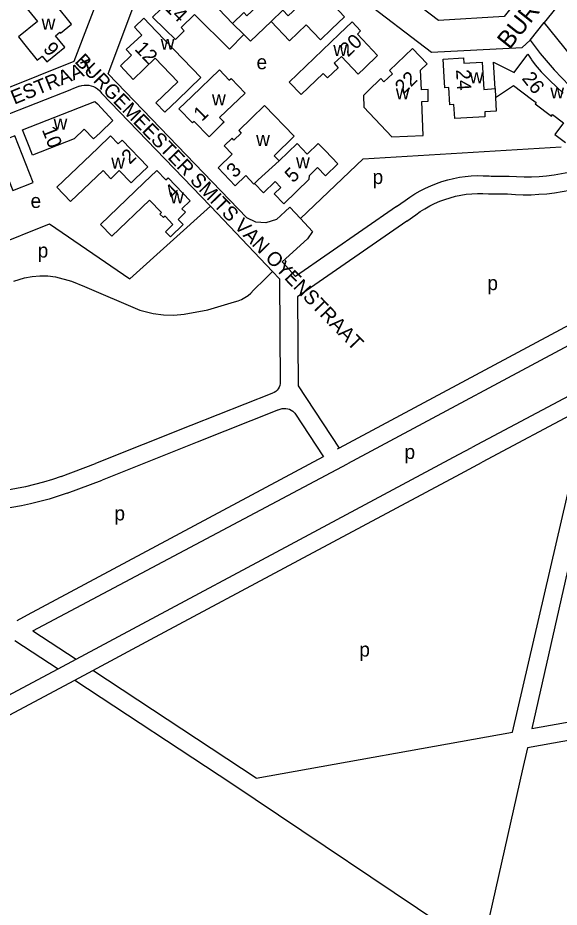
# Model space of a CAD drawing. Extents: x 159261 to 160849, y 382514 to 384534.
# Drawn here: x 159856 to 160007.7, y 382712.8 to 382961.9 of the extents above; entities that cross this region are included whole.
import ezdxf

# ---------------------------------------------------------------- set-up
doc = ezdxf.new("R2010")
doc.units = 0
for name, color, linetype in [('BLT_Basislijn', 7, 'Continuous'), ('BLT_Bebouwing', 7, 'Continuous'), ('BLT_Centroide', 7, 'Continuous'), ('BLT_Huisnummer', 7, 'Continuous'), ('BLT_Onderverdeling_panden', 7, 'Continuous'), ('BLT_Straatnaam', 7, 'Continuous'), ('BLT_Straatnaam_verkleind', 7, 'Continuous')]:
    doc.layers.add(name, color=color, linetype=linetype)

msp = doc.modelspace()

# ---------------------------------------------------------------- linework, layer by layer
at = {"layer": 'BLT_Basislijn'}
for p, q in [((160058.23, 383028.61), (160003.53, 382960.61)), ((159933.17, 382982), (159971.93, 382952.26)), ((159881.27, 382946.18), (159890.56, 382970.79)), ((159999.6, 382955.67), (160003.53, 382960.61)), ((159997.39, 382953.55), (159999.6, 382955.67)), ((159999.6, 382955.67), (160002.39, 382951.92)), ((159971.93, 382952.26), (159997.39, 382953.55)), ((160002.39, 382951.92), (160006.35, 382947.38)), ((160006.35, 382947.38), (160012.81, 382940.59)), ((159920.18, 382905.9), (159881.27, 382946.18)), ((159851.1, 382934.1), (159871.08, 382941.92)), ((159873.23, 382942.8), (159871.08, 382941.92)), ((159879.48, 382940.84), (159909.96, 382909.12)), ((159952.75, 382922.39), (160008.31, 382925.74)), ((159935.18, 382905.66), (159952.75, 382922.39)), ((159988.65, 382917.56), (159993.68, 382917.56)), ((159988.2, 382912.58), (159993.25, 382912.58)), ((159962.17, 382909.1), (159964.52, 382910.72)), ((159909.96, 382909.12), (159913.63, 382905.31)), ((159930.88, 382907.65), (159928.49, 382905.42)), ((159932.19, 382908.9), (159930.88, 382907.65)), ((159935.18, 382905.66), (159932.19, 382908.9)), ((159962.17, 382909.1), (159933.81, 382889.44)), ((159913.63, 382905.31), (159927.36, 382890.87)), ((159922.66, 382904.66), (159920.18, 382905.9)), ((159925.52, 382904.47), (159922.66, 382904.66)), ((159928.49, 382905.42), (159925.52, 382904.47)), ((159965.02, 382904.99), (159934.37, 382883.74)), ((159965.02, 382904.99), (159967.52, 382906.72)), ((159930.1, 382893.52), (159933.81, 382889.44)), ((159927.36, 382890.87), (159929.33, 382888.8)), ((159929.33, 382888.8), (159929.53, 382859.47)), ((159934.37, 382883.74), (159934.54, 382858.83)), ((160017.32, 382859.71), (159983.24, 382841.55)), ((159934.54, 382858.83), (159946.06, 382841.36)), ((159927.22, 382856.72), (159904.44, 382847.69)), ((160015.85, 382853.26), (159986.11, 382837.42)), ((159929.07, 382852.07), (159906.28, 382843.04)), ((159933.6, 382851.17), (159941.63, 382838.99)), ((159904.44, 382847.69), (159877.74, 382837.04)), ((159906.28, 382843.04), (159879.6, 382832.4)), ((159946.06, 382841.36), (159945.52, 382841.08)), ((159979.5, 382839.57), (159983.24, 382841.55)), ((159932.41, 382814.4), (159979.5, 382839.57)), ((159941.63, 382838.99), (159941.53, 382838.94)), ((159980.1, 382834.22), (159986.11, 382837.42)), ((159860.15, 382790.19), (159948.41, 382836.95)), ((159868.11, 382833.46), (159877.74, 382837.04)), ((159869.8, 382828.75), (159879.6, 382832.4)), ((159934.76, 382809.99), (159980.1, 382834.22)), ((159890.82, 382792.19), (159932.41, 382814.4)), ((159893.17, 382787.78), (159934.76, 382809.99)), ((159860.15, 382790.19), (159872.34, 382782.31)), ((159872.34, 382782.31), (159890.82, 382792.19)), ((159855.11, 382787.5), (159867.3, 382779.61)), ((159876.98, 382779.12), (159893.17, 382787.78)), ((159867.3, 382779.61), (159872.34, 382782.31)), ((159849.56, 382770.13), (159867.3, 382779.61)), ((159871.96, 382776.44), (159876.98, 382779.12)), ((159922.81, 382748.95), (159876.98, 382779.12)), ((159852.2, 382765.87), (159871.96, 382776.44)), ((159998.83, 382757.49), (159997.36, 382750.97)), ((159997.36, 382750.97), (159983.99, 382691.71))]:
    msp.add_line(p, q, dxfattribs=at)
for points in [[(160042.91, 383029.03), (160043.3, 383028.51), (160043.47, 383027.9), (160043.44, 383027.23), (160043.27, 383026.57), (160040.7, 383022.91), (159992.33, 382962.32), (159973.92, 382961.19), (159954.84, 382975.74), (159937.58, 382989.45), (159937.15, 382990.12), (160001.27, 383055.05), (160002.23, 383055.6), (160003.22, 383055.89), (160004.3, 383055.97), (160005.53, 383055.68), (160014.56, 383049.24)], [(159804.96, 382923.13), (159812.17, 382925.83), (159871.81, 382949.78), (159881.19, 382974.39)], [(160023.71, 382939.02), (160018.92, 382943.04), (160012.93, 382948.97), (160003.53, 382960.61)], [(159873.23, 382942.8), (159873.88, 382942.97), (159874.54, 382943.07), (159875.21, 382943.08), (159875.87, 382943.02), (159876.52, 382942.87), (159877.15, 382942.65), (159877.75, 382942.36), (159878.31, 382942), (159878.83, 382941.57), (159879.29, 382941.08), (159879.48, 382940.84)], [(159964.52, 382910.72), (159965.88, 382911.7), (159967.29, 382912.6), (159968.74, 382913.43), (159970.22, 382914.2), (159971.74, 382914.89), (159973.3, 382915.51), (159974.88, 382916.06), (159976.48, 382916.53), (159978.1, 382916.92), (159979.75, 382917.23), (159981.4, 382917.47), (159983.07, 382917.62), (159984.74, 382917.7), (159986.41, 382917.69), (159988.08, 382917.61), (159988.65, 382917.56)], [(159993.68, 382917.56), (159995.78, 382917.42), (159997.88, 382917.36), (159999.99, 382917.38), (160002.09, 382917.48), (160004.19, 382917.66), (160006.28, 382917.92), (160008.36, 382918.26), (160010.42, 382918.67), (160012.47, 382919.17), (160013.15, 382919.35)], [(159993.25, 382912.58), (159995.44, 382912.43), (159997.64, 382912.36), (159999.84, 382912.37), (160002.04, 382912.47), (160004.23, 382912.64), (160006.41, 382912.89), (160008.58, 382913.22), (160010.74, 382913.63), (160012.89, 382914.11), (160014.47, 382914.53)], [(159967.52, 382906.72), (159968.78, 382907.62), (159970.09, 382908.45), (159971.44, 382909.21), (159972.82, 382909.9), (159974.24, 382910.52), (159975.69, 382911.06), (159977.16, 382911.53), (159978.66, 382911.92), (159980.18, 382912.23), (159981.7, 382912.47), (159983.24, 382912.62), (159984.79, 382912.7), (159986.34, 382912.69), (159987.88, 382912.61), (159988.2, 382912.58)], [(159848.75, 382898.48), (159848.97, 382897.9), (159864.82, 382904.2), (159887.39, 382888.81), (159909.96, 382909.12)], [(159935.18, 382905.66), (159938.58, 382902.08), (159937.14, 382900), (159930.1, 382893.52)], [(159854.89, 382888.14), (159857.84, 382889.09), (159859.99, 382889.49), (159862.17, 382889.67), (159864.36, 382889.61), (159866.52, 382889.33), (159871, 382888.12), (159874.69, 382886.66), (159890.22, 382879.99), (159893.9, 382879.06), (159896.8, 382878.69), (159899.73, 382878.62), (159902.65, 382878.86), (159909.22, 382880.12), (159916.71, 382882.33), (159917.72, 382882.63), (159918.71, 382883.03), (159919.64, 382883.54), (159920.52, 382884.14), (159921.33, 382884.83), (159922.06, 382885.6), (159925.3, 382888.82), (159927.36, 382890.87)], [(160022.51, 382882.25), (159946.06, 382841.36)], [(160021.02, 382875.78), (159948.41, 382836.95)], [(159929.53, 382859.47), (159929.43, 382858.97), (159929.25, 382858.48), (159928.99, 382858.04), (159928.67, 382857.63), (159928.29, 382857.28), (159927.87, 382856.99), (159927.4, 382856.78), (159927.22, 382856.72)], [(160021.17, 382856.09), (160000.04, 382762.82), (160136.27, 382787.12), (160144.29, 382788.53)], [(159922.81, 382748.95), (159994.67, 382761.8), (160015.85, 382853.26)], [(159929.07, 382852.07), (159929.55, 382852.29), (159930.06, 382852.44), (159930.59, 382852.52), (159931.12, 382852.51), (159931.65, 382852.42), (159932.16, 382852.26), (159932.64, 382852.02), (159933.07, 382851.71), (159933.46, 382851.34), (159933.6, 382851.17)], [(159941.53, 382838.94), (159858.63, 382794.61), (159855.75, 382793.04)], [(159868.11, 382833.46), (159865.67, 382832.63), (159863.19, 382831.87), (159860.69, 382831.19), (159858.18, 382830.58), (159855.64, 382830.06), (159853.09, 382829.61), (159850.53, 382829.24), (159848.5, 382829.01)], [(159869.8, 382828.75), (159867.28, 382827.89), (159864.73, 382827.11), (159862.16, 382826.4), (159859.57, 382825.77), (159856.97, 382825.22), (159854.34, 382824.75), (159851.71, 382824.35), (159849.02, 382824.03)], [(160137.38, 382782.24), (160115.57, 382778.37), (159998.83, 382757.49)], [(159871.96, 382776.44), (159915.96, 382747.47), (159981.1, 382703.75), (159977.76, 382688.38)]]:
    msp.add_lwpolyline(points, dxfattribs=at)
at = {"layer": 'BLT_Bebouwing'}
for p, q in [((159921.16, 382955.33), (159926.98, 382960.92)), ((159921.16, 382955.33), (159919.29, 382957.19)), ((160002.7, 382946.81), (160005.09, 382944.37)), ((160005.09, 382944.37), (160008.85, 382940.79))]:
    msp.add_line(p, q, dxfattribs=at)
for points in [[(159916.13, 382960.32), (159919.33, 382963.35), (159920.21, 382962.42), (159923.87, 382965.89), (159920.76, 382969.09), (159920.25, 382968.59), (159917.25, 382971.68), (159918.39, 382972.78), (159914.88, 382976.4), (159916.39, 382977.86), (159919.89, 382974.24), (159923.13, 382977.38), (159924.66, 382975.81), (159925.6, 382976.73), (159926.86, 382975.43), (159930.52, 382978.98), (159936.42, 382972.89), (159932.24, 382968.86), (159933.66, 382967.34), (159930.23, 382964.04)], [(159919.29, 382957.19), (159915.3, 382953.17), (159905.51, 382962.88), (159901.8, 382959.15), (159902.65, 382958.3), (159900.16, 382955.79), (159897.31, 382958.61), (159893.76, 382962.13), (159896.1, 382964.36), (159895.28, 382965.22), (159898.93, 382968.72), (159899.76, 382967.85), (159904.62, 382972.46), (159916.13, 382960.32)], [(159926.98, 382960.92), (159932.16, 382955.49), (159936.83, 382959.95), (159940.81, 382955.77), (159943.94, 382958.76), (159947.55, 382962.21), (159944.65, 382965.23), (159946.26, 382966.79), (159941.35, 382971.93), (159934.11, 382965), (159934.29, 382964.79), (159931.77, 382962.42), (159930.23, 382964.04)], [(159860.73, 382971.35), (159856.08, 382967.55), (159861.49, 382960.92), (159856.13, 382956.55), (159858.28, 382953.91), (159861.44, 382950.04), (159862.8, 382951.17), (159864.16, 382949.56), (159869.15, 382953.66), (159866.51, 382956.9), (159867.72, 382957.88), (159867.95, 382957.6), (159871.06, 382960.14), (159866.84, 382965.31), (159866.13, 382964.72), (159860.73, 382971.35)], [(159900.83, 382938.91), (159907.31, 382945.18), (159894.76, 382958.21), (159891.29, 382961.81), (159888.65, 382959.26), (159890.71, 382957.09), (159886.37, 382953.02), (159887.88, 382951.45), (159884.74, 382948.42), (159888.35, 382944.66), (159894.5, 382950.57), (159900.81, 382943.99), (159894.67, 382938.1), (159897.23, 382935.44), (159900.83, 382938.91)], [(159953.26, 382947.88), (159951.4, 382946.08), (159946.68, 382951.1), (159944.62, 382949.17), (159945.78, 382947.93), (159942.81, 382945.14), (159941.6, 382946.35), (159935.38, 382940.4), (159932.01, 382943.9), (159946.06, 382957.31), (159949.68, 382960.76), (159952.06, 382958.27), (159951.15, 382957.33), (159956.84, 382951.36), (159953.26, 382947.88)], [(159970.97, 382938.57), (159970.97, 382941.8), (159969.12, 382941.76), (159968.86, 382947.24), (159970.76, 382949.01), (159966.6, 382953.34), (159960.13, 382947.17), (159960.98, 382946.26), (159958.6, 382943.95), (159957.75, 382944.89), (159954.14, 382941.43), (159952.84, 382940.19), (159952.98, 382936.87), (159960.85, 382928.58), (159969.64, 382928.96), (159969.25, 382938.5), (159970.97, 382938.57)], [(159989.9, 382939.63), (159990.07, 382935.74), (159986.85, 382935.55), (159986.93, 382934.2), (159978.46, 382933.66), (159978.21, 382937.63), (159977.09, 382937.56), (159976.79, 382942.39), (159975.68, 382942.31), (159975.5, 382945.34), (159975.21, 382950.33), (159980.91, 382950.67), (159981.03, 382949.2), (159986.12, 382949.51), (159986.57, 382941.87), (159989.78, 382942.08)], [(159989.78, 382942.08), (159989.32, 382949.49), (159995.13, 382946.61), (159998.93, 382951.68)], [(159998.93, 382951.68), (159999.89, 382950.28), (160000, 382950.12)], [(160000, 382950.12), (160001.03, 382948.77), (160002.12, 382947.46), (160002.7, 382946.81)], [(159913.81, 382932.69), (159913.3, 382932.19), (159913.18, 382932.08), (159909.59, 382928.61), (159905.37, 382932.91), (159904.95, 382932.51), (159901.14, 382936.45), (159904.76, 382939.91), (159912.54, 382947.34), (159915.25, 382944.48), (159915.74, 382944.94), (159919.67, 382940.8), (159912.53, 382934.03), (159913.81, 382932.69)], [(159989.9, 382939.63), (159994.95, 382942.92), (160000, 382939.16), (160001.28, 382938.21), (160000.99, 382937.83), (160005.57, 382934.39), (160005.85, 382934.79), (160008.97, 382932.45), (160006.52, 382929.19), (160009.5, 382926.95)], [(159879.02, 382929.73), (159877.19, 382927.98), (159874.56, 382930.72), (159871.76, 382928.03), (159860.1, 382923.47), (159859.15, 382925.89), (159857.33, 382930.55), (159877.54, 382938.46), (159878.3, 382937.78), (159882.63, 382933.19), (159879.02, 382929.73)], [(159929.22, 382921.83), (159927.82, 382923.28), (159933.46, 382928.72), (159925.15, 382937.34), (159925.15, 382937.33), (159925.16, 382937.32), (159921.52, 382933.81), (159917.93, 382930.32), (159918.6, 382929.64), (159916.54, 382927.68), (159916.06, 382928.22), (159913.83, 382926.03), (159916.05, 382923.73), (159912.1, 382919.93), (159916.93, 382914.89), (159919.86, 382917.72), (159922.16, 382915.34), (159922.3, 382915.48)], [(159847.59, 382925.89), (159847.89, 382925.13), (159842.43, 382923), (159846.05, 382913.77), (159853.39, 382916.64), (159854.6, 382913.55), (159860.26, 382915.77), (159855.15, 382928.82), (159847.59, 382925.89)], [(159888.82, 382916.7), (159887.74, 382915.66), (159884.42, 382919.13), (159882.08, 382916.83), (159879.86, 382919.15), (159870.78, 382910.47), (159866.95, 382914.47), (159878.37, 382925.4), (159881.98, 382928.86), (159884.13, 382926.62), (159885.22, 382927.66), (159892.43, 382920.16), (159888.82, 382916.7)], [(159922.3, 382915.48), (159924.83, 382912.87), (159928.1, 382916.05), (159929.69, 382914.41), (159927.83, 382912.6), (159930.55, 382909.8), (159937.69, 382916.69), (159937.72, 382917.78), (159939.98, 382919.99), (159942.22, 382917.66), (159945.65, 382921.05), (159942.18, 382924.64), (159940.17, 382926.73), (159937.08, 382923.75), (159934.24, 382926.69), (159929.22, 382921.83)], [(159900.93, 382905.46), (159902.3, 382904.01), (159898.75, 382900.54), (159897.34, 382901.98), (159899.45, 382904.05), (159897.24, 382906.37), (159896.8, 382905.95), (159895.79, 382906.95), (159896.24, 382907.39), (159892.87, 382910.83), (159882.3, 382900.73), (159879.16, 382904.01), (159891.33, 382915.66), (159894.94, 382919.12), (159897.45, 382916.51), (159898.09, 382917.11), (159904.32, 382910.65), (159901.99, 382908.4), (159902.99, 382907.43), (159900.93, 382905.46)]]:
    msp.add_lwpolyline(points, dxfattribs=at)
at = {"layer": 'BLT_Onderverdeling_panden'}
for p, q in [((159926.98, 382960.92), (159930.23, 382964.04)), ((159919.29, 382957.19), (159916.13, 382960.32)), ((159989.78, 382942.08), (159989.9, 382939.63))]:
    msp.add_line(p, q, dxfattribs=at)
msp.add_lwpolyline([(159929.22, 382921.83), (159923.31, 382916.49), (159922.3, 382915.48)], dxfattribs=at)

# ---------------------------------------------------------------- texts
at = {"layer": 'BLT_Centroide'}
for s, p in [('w', (159862.64, 382958.58)), ('w', (159896.03, 382952.94)), ('w', (159944.42, 382951.2)), ('e', (159922.9, 382947.5)), ('w', (159982.64, 382943.59)), ('w', (159961.93, 382939.12)), ('w', (160005.25, 382939.31)), ('w', (159910.41, 382937.36)), ('w', (159866, 382930.62)), ('w', (159922.78, 382926.03)), ('w', (159882.16, 382919.69)), ('w', (159933.97, 382919.77)), ('p', (159955.42, 382915.36)), ('w', (159898.66, 382909.94)), ('e', (159859.55, 382908.65)), ('p', (159861.55, 382894.76)), ('p', (159987.6, 382885.64)), ('p', (159964.38, 382838.35)), ('p', (159883.06, 382821.14)), ('p', (159951.69, 382783.01))]:
    msp.add_text(s, height=4, dxfattribs=at).set_placement(p)
at = {"layer": 'BLT_Huisnummer'}
for s, rotation, p in [('14', 315.235, (159896.89, 382964.52)), ('20', 44.1075, (159948.55, 382950.74)), ('9', 309.178, (159862.89, 382953.11)), ('12', 313.8175, (159888.51, 382953.02)), ('24', 273.3287, (159978.81, 382947.37)), ('22', 44.0112, (159964.02, 382940.3)), ('26', 308.1756, (159997.1, 382944.88)), ('1', 44.054, (159907.57, 382932.71)), ('10', 291.3609, (159862.67, 382930.6)), ('2', 43.8087, (159887.35, 382920.71)), ('3', 43.8177, (159916.77, 382916.86)), ('5', 43.9836, (159933.13, 382915.49)), ('4', 43.6558, (159899.47, 382910.88))]:
    msp.add_text(s, height=4, rotation=rotation, dxfattribs=at).set_placement(p)
at = {"layer": 'BLT_Straatnaam'}
msp.add_text('BURGEMEESTER WITTESTRAAT', height=5, rotation=51.4824, dxfattribs=at).set_placement((159993.82, 382952.82))
at = {"layer": 'BLT_Straatnaam_verkleind'}
for s, rotation, p in [('BURGEMEESTER SMITS VAN OYENSTRAAT', 314.1072, (159871.73, 382949.51)), ('BURGEMEESTER WITTESTRAAT', 22.2188, (159799.99, 382915.09))]:
    msp.add_text(s, height=4, rotation=rotation, dxfattribs=at).set_placement(p)

doc.saveas('drawing.dxf')
